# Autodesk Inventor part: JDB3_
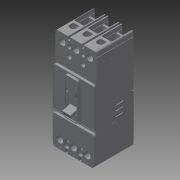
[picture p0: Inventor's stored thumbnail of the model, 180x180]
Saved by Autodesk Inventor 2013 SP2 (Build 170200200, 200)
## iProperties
Created: 2014-08
Part Number: JDB3_
Material: Generic
Document SubType Name: Modeling
Designer: EM/EM
Density: 1 g/cm^3
Description: TYPE JDB THERMAL MAGNETIC CIRCUIT BREAKERS THREE POLE, SERIES C
MXEDIT: false
MXINVTNRV: INV Versioned Component|JDB3_|004.0
Author: EM/EM
Revision Number: 004
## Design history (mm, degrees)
derived "JD3_.iam"
node "L1"
node "L2"
node "L3"
node "T1"
node "T2"
node "T3"
sketch "Sketch1"
  geometry: C1 r 10.795 at (8.89, 11.913) reference; C2 r 10.795 at (8.89, 11.913); 1 further point
  constraints: 1 centre point, 1 coincident, 1 concentric
extrude "Extrusion1" cut sketch "Sketch1" distance "d1" = 9.525; taper "d2" = 0 deg
sketch "Sketch2"
  geometry: C1 r 6.35 at (0, 0) reference; C2 r 6.35 at (0, 0); 1 further point
  constraints: 1 centre point, 1 coincident, 1 concentric
extrude "Extrusion2" cut sketch "Sketch2" distance "d3" = 9.525; taper "d5" = 0 deg; dims "d4" = 4.7752, "d6" = 0
sketch "Sketch3"
  geometry: C1 r 10.795 at (11.494, 11.913) reference; C2 r 10.795 at (11.494, 11.913); 1 further point
  constraints: 1 centre point, 1 coincident, 1 concentric
extrude "Extrusion3" cut sketch "Sketch3" distance "d7" = 9.525; taper "d8" = 0 deg
sketch "Sketch4"
  geometry: C1 r 6.35 at (0, 0) reference; C2 r 6.35 at (0, 0); 1 further point
  constraints: 1 centre point, 1 coincident, 1 concentric
extrude "Extrusion4" cut sketch "Sketch4" distance "d9" = 9.525; taper "d11" = 0 deg; dims "d10" = 4.7752, "d12" = 0
sketch "Sketch5"
  geometry: C1 r 10.795 at (11.494, 11.913) reference; C2 r 10.795 at (11.494, 11.913); 1 further point
  constraints: 1 centre point, 1 coincident, 1 concentric
extrude "Extrusion5" cut sketch "Sketch5" distance "d13" = 9.525; taper "d15" = 0 deg; dims "d14" = 4.7752, "d16" = 0
sketch "Sketch6"
  geometry: C1 r 6.35 at (0, 0) reference; C2 r 6.35 at (0, 0); 1 further point
  constraints: 1 centre point, 1 coincident, 1 concentric
extrude "Extrusion6" cut sketch "Sketch6" distance "d17" = 9.525; taper "d19" = 0 deg; dims "d18" = 4.7752, "d20" = 0
sketch "Sketch7"
  geometry: C1 r 8.738 at (-0.038, 0) reference; C2 r 8.738 at (-0.038, 0); 1 further point
  constraints: 1 centre point, 1 coincident, 1 concentric
extrude "Extrusion7" cut sketch "Sketch7" distance "d21" = 9.525; taper "d23" = 0 deg; dims "d22" = 4.7752, "d24" = 0
sketch "Sketch8"
  geometry: C1 r 8.738 at (-0.013, 0) reference; C2 r 8.738 at (-0.013, 0); 1 further point
  constraints: 1 centre point, 1 coincident, 1 concentric
extrude "Extrusion8" cut sketch "Sketch8" distance "d25" = 9.525; taper "d27" = 0 deg; dims "d26" = 4.7752, "d28" = 0
sketch "Sketch9"
  geometry: C1 r 8.738 at (0.013, 0) reference; C2 r 8.738 at (0.013, 0); 1 further point
  constraints: 1 centre point, 1 coincident, 1 concentric
extrude "Extrusion9" cut sketch "Sketch9" distance "d29" = 9.525; taper "d31" = 0 deg; dims "d30" = 4.7752, "d32" = 0
body "Solid1"
node "JD3_.ipt:1"
